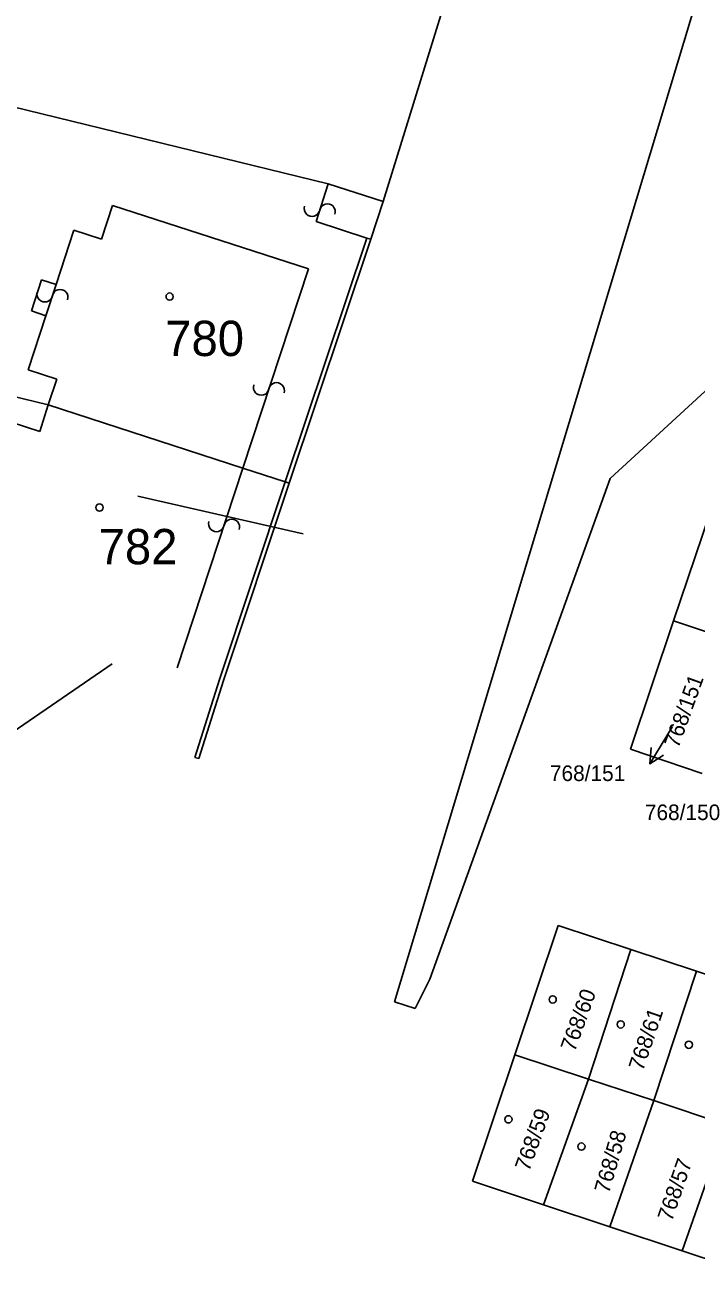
# Model space of a CAD drawing. Extents: x -469926 to -462499, y -1098642 to -1092733.
# Drawn here: x -465590.7 to -465558.3, y -1095068.4 to -1095008.2 of the extents above; entities that cross this region are included whole.
import ezdxf

# ---------------------------------------------------------------- set-up
doc = ezdxf.new("R2010")
doc.units = 0
for name, color, linetype in [('Vrstva 1', 7, 'Continuous'), ('Vrstva 16', 7, 'Continuous'), ('Vrstva 25', 7, 'Continuous'), ('Vrstva 4', 7, 'Continuous'), ('Vrstva 50', 7, 'Continuous'), ('Vrstva 51', 7, 'Continuous')]:
    doc.layers.add(name, color=color, linetype=linetype)

msp = doc.modelspace()

# ---------------------------------------------------------------- linework, layer by layer
at = {"layer": 'Vrstva 1'}
for p, q in [((-465572.88, -1095055.23), (-465553.87, -1094992.09)), ((-465568.37, -1095000.37), (-465573.44, -1095016.72)), ((-465576.07, -1095015.86), (-465598.3, -1095010.43)), ((-465573.44, -1095016.72), (-465576.07, -1095015.86)), ((-465573.44, -1095016.72), (-465574.03, -1095018.53)), ((-465562.51, -1095030.04), (-465549.15, -1095017.74)), ((-465574.03, -1095018.53), (-465577.95, -1095030.27)), ((-465589.54, -1095026.5), (-465591.38, -1095026.05)), ((-465580.18, -1095029.55), (-465589.54, -1095026.5)), ((-465578.14, -1095030.21), (-465580.18, -1095029.55)), ((-465581.11, -1095039.77), (-465577.95, -1095030.27)), ((-465577.95, -1095030.27), (-465578.14, -1095030.21)), ((-465571.18, -1095054.14), (-465562.51, -1095030.04)), ((-465557.39, -1095030.74), (-465559.47, -1095036.89)), ((-465559.47, -1095036.89), (-465561.54, -1095043.06)), ((-465559.47, -1095036.89), (-465556.03, -1095038.05)), ((-465591.787, -1095042.615), (-465586.468, -1095038.964)), ((-465591.787, -1095042.615), (-465586.468, -1095038.964)), ((-465582.3, -1095043.52), (-465581.11, -1095039.77)), ((-465582.49, -1095043.46), (-465582.3, -1095043.52)), ((-465561.54, -1095043.06), (-465558.1, -1095044.23)), ((-465565.01, -1095051.55), (-465567.1, -1095057.77)), ((-465561.52, -1095052.71), (-465565.01, -1095051.55)), ((-465561.52, -1095052.71), (-465563.56, -1095058.94)), ((-465558.37, -1095053.75), (-465561.52, -1095052.71)), ((-465558.37, -1095053.75), (-465560.42, -1095059.98)), ((-465554.87, -1095054.91), (-465558.37, -1095053.75)), ((-465571.9, -1095055.54), (-465571.18, -1095054.14)), ((-465572.88, -1095055.23), (-465571.9, -1095055.54)), ((-465567.1, -1095057.77), (-465569.14, -1095063.86)), ((-465567.1, -1095057.77), (-465563.56, -1095058.94)), ((-465563.56, -1095058.94), (-465565.73, -1095064.99)), ((-465563.56, -1095058.94), (-465560.42, -1095059.98)), ((-465560.42, -1095059.98), (-465562.53, -1095066.05)), ((-465560.42, -1095059.98), (-465556.93, -1095061.14)), ((-465556.93, -1095061.14), (-465559.06, -1095067.2)), ((-465569.14, -1095063.86), (-465565.73, -1095064.99)), ((-465565.73, -1095064.99), (-465562.53, -1095066.05)), ((-465562.53, -1095066.05), (-465559.06, -1095067.2)), ((-465559.06, -1095067.2), (-465555.55, -1095068.37))]:
    msp.add_line(p, q, dxfattribs=at)
at = {"layer": 'Vrstva 16'}
for p, q in [((-465577.282, -1095032.709), (-465585.228, -1095030.899)), ((-465559.52, -1095041.97), (-465560.61, -1095043.765))]:
    msp.add_line(p, q, dxfattribs=at)
msp.add_lwpolyline([(-465559.947, -1095043.348), (-465560.61, -1095043.765), (-465560.546, -1095042.985)], dxfattribs=at)
at = {"layer": 'Vrstva 25'}
for centre in [(-465583.7, -1095021.29), (-465587.07, -1095031.44), (-465565.28, -1095055.11), (-465562.01, -1095056.31), (-465558.73, -1095057.29), (-465567.41, -1095060.88), (-465563.9, -1095062.19)]:
    msp.add_circle(centre, 0.175, dxfattribs=at)
at = {"layer": 'Vrstva 4'}
for p, q in [((-465576.66, -1095017.67), (-465576.07, -1095015.86)), ((-465586.45, -1095016.91), (-465586.98, -1095018.52)), ((-465577.03, -1095019.95), (-465586.45, -1095016.91)), ((-465574.22, -1095018.47), (-465576.66, -1095017.67)), ((-465588.31, -1095018.1), (-465589.16, -1095020.71)), ((-465586.98, -1095018.52), (-465588.31, -1095018.1)), ((-465578.14, -1095030.21), (-465574.22, -1095018.47)), ((-465574.03, -1095018.53), (-465574.22, -1095018.47)), ((-465580.18, -1095029.55), (-465577.03, -1095019.95)), ((-465589.86, -1095020.48), (-465590.35, -1095021.98)), ((-465589.16, -1095020.71), (-465589.86, -1095020.48)), ((-465589.16, -1095020.71), (-465589.65, -1095022.21)), ((-465589.65, -1095022.21), (-465590.5, -1095024.82)), ((-465590.35, -1095021.98), (-465589.65, -1095022.21)), ((-465590.5, -1095024.82), (-465589.13, -1095025.26)), ((-465589.13, -1095025.26), (-465589.54, -1095026.5)), ((-465589.54, -1095026.5), (-465589.95, -1095027.78)), ((-465589.95, -1095027.78), (-465591.32, -1095027.33)), ((-465583.34, -1095039.16), (-465580.18, -1095029.55)), ((-465581.3, -1095039.72), (-465578.14, -1095030.21)), ((-465582.49, -1095043.46), (-465581.3, -1095039.72))]:
    msp.add_line(p, q, dxfattribs=at)
at = {"layer": 'Vrstva 51'}
for centre, radius, start, end in [((-465576.853, -1095017.055), 0.376, 161.99036, 348.30149), ((-465576.115, -1095017.204), 0.377, 341.31432, 168.97753), ((-465589.705, -1095021.173), 0.376, 161.99036, 348.30149), ((-465588.966, -1095021.321), 0.377, 341.31432, 168.97753), ((-465579.296, -1095025.657), 0.376, 161.99036, 348.30149), ((-465578.558, -1095025.805), 0.377, 341.31432, 168.97753), ((-465581.454, -1095032.227), 0.376, 161.99036, 348.30149), ((-465580.716, -1095032.376), 0.377, 341.31432, 168.97753)]:
    msp.add_arc(centre, radius, start, end, dxfattribs=at)

# ---------------------------------------------------------------- texts
at = {"layer": 'Vrstva 50'}
for s, height, p in [('780', 1.7, (-465583.915, -1095024.15)), ('782', 1.7, (-465587.117, -1095034.17)), ('768/151', 0.75, (-465565.414, -1095044.6)), ('768/150', 0.75, (-465560.847, -1095046.48))]:
    msp.add_text(s, height=height, dxfattribs=at).set_placement(p)
for s, rotation, p in [('768/151', 70.191, (-465559.234, -1095043.058)), ('768/60', 70.191, (-465564.221, -1095057.667)), ('768/61', 71.1, (-465560.945, -1095058.593)), ('768/59', 70.191, (-465566.416, -1095063.421)), ('768/58', 73.8, (-465562.576, -1095064.487)), ('768/57', 71.1, (-465559.55, -1095065.832))]:
    msp.add_text(s, height=0.75, rotation=rotation, dxfattribs=at).set_placement(p)

doc.saveas('drawing.dxf')
